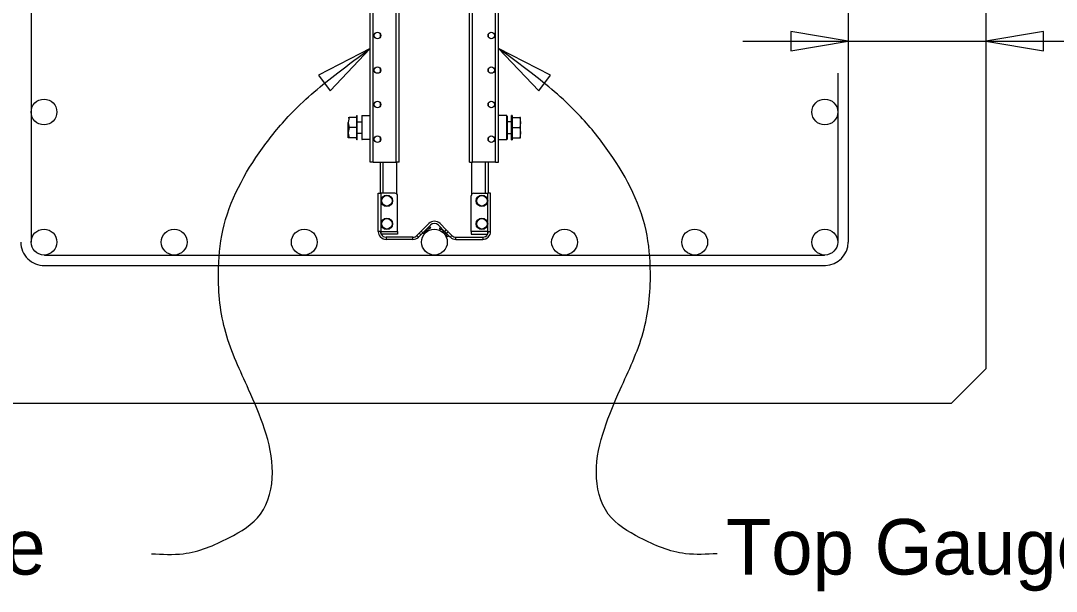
# Model space of a CAD drawing. Extents: x 0 to 36.1, y -3.7 to 15.
# Drawn here: x 2.543 to 4.42, y 5.937 to 6.972 of the extents above; entities that cross this region are included whole.
import ezdxf

# ---------------------------------------------------------------- set-up
doc = ezdxf.new("R2010")
doc.units = 0
for name, color, linetype in [('Leader', 7, 'Continuous'), ('Miscellaneous', 7, 'Continuous'), ('PileConc', 7, 'Continuous'), ('PlotBorder_dp', 7, 'Continuous'), ('PrestressSteel', 7, 'Continuous')]:
    doc.layers.add(name, color=color, linetype=linetype)

msp = doc.modelspace()

# ---------------------------------------------------------------- linework, layer by layer
at = {"layer": 'Leader'}
for points in [[(2.7804, 6.0056), (2.8378, 6.0056), (2.9204, 6.0343), (2.9778, 6.0774), (2.9994, 6.1527), (2.985, 6.2317), (2.9563, 6.3035), (2.9147, 6.4066), (2.9015, 6.5152), (2.9094, 6.592), (2.9814, 6.7414), (3.0353, 6.8061), (3.1178, 6.8779), (3.1768, 6.9218)], [(3.8057, 6.0056), (3.7483, 6.0056), (3.6657, 6.0343), (3.6083, 6.0774), (3.5867, 6.1527), (3.6011, 6.2317), (3.6298, 6.3035), (3.6714, 6.4066), (3.6846, 6.5152), (3.6767, 6.592), (3.6047, 6.7414), (3.5508, 6.8061), (3.4683, 6.8779), (3.4093, 6.9218)]]:
    msp.add_spline(points, degree=3, dxfattribs=at)
at = {"layer": 'Miscellaneous'}
for p, q in [((3.1768, 6.7159), (3.1768, 7.7123)), ((3.4093, 6.7159), (3.4093, 7.7123)), ((3.1821, 6.7159), (3.1821, 7.2312)), ((3.2239, 6.7159), (3.2239, 7.2284)), ((3.2292, 6.7159), (3.2292, 7.2284)), ((3.3569, 6.7159), (3.3569, 7.2284)), ((3.3622, 6.7159), (3.3622, 7.2284)), ((3.404, 6.7159), (3.404, 7.2312)), ((3.1951, 6.9429), (3.1951, 6.9481)), ((3.391, 6.9429), (3.391, 6.9481)), ((3.1951, 6.8802), (3.1951, 6.8855)), ((3.391, 6.8802), (3.391, 6.8855)), ((3.1951, 6.8176), (3.1951, 6.8229)), ((3.391, 6.8176), (3.391, 6.8229)), ((3.1383, 6.7968), (3.1366, 6.7876)), ((3.1366, 6.7968), (3.1383, 6.7968)), ((3.1519, 6.7968), (3.1383, 6.7968)), ((3.1515, 6.7968), (3.1521, 6.8004)), ((3.1519, 6.7968), (3.1519, 6.7785)), ((3.1521, 6.8004), (3.1533, 6.8004)), ((3.1521, 6.8004), (3.1521, 6.7566)), ((3.1533, 6.7566), (3.1533, 6.8004)), ((3.1613, 6.7995), (3.1613, 6.7575)), ((3.162, 6.8002), (3.1768, 6.8002)), ((3.162, 6.7568), (3.162, 6.8002)), ((3.4241, 6.8002), (3.4093, 6.8002)), ((3.4241, 6.7568), (3.4241, 6.8002)), ((3.4247, 6.7995), (3.4247, 6.7575)), ((3.434, 6.8004), (3.4327, 6.8004)), ((3.4327, 6.7566), (3.4327, 6.8004)), ((3.4346, 6.7968), (3.434, 6.8004)), ((3.434, 6.8004), (3.434, 6.7566)), ((3.4341, 6.7968), (3.4341, 6.7785)), ((3.4341, 6.7968), (3.4478, 6.7968)), ((3.4478, 6.7968), (3.4494, 6.7876)), ((3.4494, 6.7968), (3.4478, 6.7968)), ((3.4494, 6.7876), (3.4494, 6.7968)), ((3.1366, 6.7694), (3.1366, 6.7876)), ((3.1383, 6.7785), (3.1366, 6.7694)), ((3.1519, 6.7785), (3.1383, 6.7785)), ((3.1519, 6.7785), (3.1519, 6.7602)), ((3.1533, 6.7889), (3.1613, 6.7889)), ((3.4327, 6.7889), (3.4247, 6.7889)), ((3.4341, 6.7785), (3.4341, 6.7602)), ((3.4341, 6.7785), (3.4478, 6.7785)), ((3.4478, 6.7785), (3.4494, 6.7694)), ((3.4494, 6.7694), (3.4494, 6.7876)), ((3.1366, 6.7602), (3.1366, 6.7694)), ((3.1383, 6.7602), (3.1366, 6.7602)), ((3.1519, 6.7602), (3.1383, 6.7602)), ((3.1521, 6.7566), (3.1515, 6.7602)), ((3.1613, 6.7681), (3.1533, 6.7681)), ((3.1951, 6.755), (3.1951, 6.7603)), ((3.391, 6.755), (3.391, 6.7603)), ((3.4247, 6.7681), (3.4327, 6.7681)), ((3.434, 6.7566), (3.4346, 6.7602)), ((3.4341, 6.7602), (3.4478, 6.7602)), ((3.4478, 6.7602), (3.4494, 6.7602)), ((3.4494, 6.7602), (3.4494, 6.7694)), ((3.1533, 6.7566), (3.1521, 6.7566)), ((3.1768, 6.7568), (3.162, 6.7568)), ((3.4093, 6.7568), (3.4241, 6.7568)), ((3.4327, 6.7566), (3.434, 6.7566)), ((3.1821, 6.7159), (3.1768, 6.7159)), ((3.1821, 6.7159), (3.2239, 6.7159)), ((3.1951, 6.6596), (3.1951, 6.7159)), ((3.2004, 6.6596), (3.2004, 6.7159)), ((3.2292, 6.7159), (3.2239, 6.7159)), ((3.2252, 6.6579), (3.2252, 6.7159)), ((3.3569, 6.7159), (3.3622, 6.7159)), ((3.3609, 6.6579), (3.3609, 6.7159)), ((3.404, 6.7159), (3.3622, 6.7159)), ((3.3857, 6.6596), (3.3857, 6.7159)), ((3.391, 6.6596), (3.391, 6.7159)), ((3.404, 6.7159), (3.4093, 6.7159)), ((3.1911, 6.6596), (3.1963, 6.6596)), ((3.1911, 6.5902), (3.1911, 6.6596)), ((3.2214, 6.6596), (3.1963, 6.6596)), ((3.1963, 6.5902), (3.1963, 6.6596)), ((3.2264, 6.5902), (3.2264, 6.6546)), ((3.3597, 6.5902), (3.3597, 6.6546)), ((3.3647, 6.6596), (3.3897, 6.6596)), ((3.3897, 6.5902), (3.3897, 6.6596)), ((3.395, 6.6596), (3.3897, 6.6596)), ((3.395, 6.5902), (3.395, 6.6596)), ((3.1963, 6.5902), (3.1911, 6.5902)), ((3.1963, 6.585), (3.1963, 6.5902)), ((3.1963, 6.5902), (3.2264, 6.5902)), ((3.2264, 6.5902), (3.2264, 6.585)), ((3.2692, 6.5907), (3.2828, 6.6043)), ((3.2721, 6.5879), (3.2692, 6.5907)), ((3.2857, 6.6015), (3.2721, 6.5879)), ((3.2771, 6.5911), (3.2786, 6.5896)), ((3.2786, 6.5926), (3.2801, 6.5911)), ((3.2811, 6.5951), (3.2802, 6.596)), ((3.2807, 6.5947), (3.2821, 6.5932)), ((3.2827, 6.5967), (3.2842, 6.5953)), ((3.2852, 6.5992), (3.2843, 6.6001)), ((3.2848, 6.5988), (3.2863, 6.5974)), ((3.3116, 6.5902), (3.3004, 6.6015)), ((3.3034, 6.5967), (3.302, 6.5952)), ((3.3039, 6.5979), (3.3031, 6.5971)), ((3.3033, 6.6043), (3.3145, 6.5931)), ((3.3055, 6.5946), (3.3041, 6.5931)), ((3.3091, 6.591), (3.3076, 6.5896)), ((3.311, 6.5909), (3.3101, 6.59)), ((3.3145, 6.5931), (3.3116, 6.5902)), ((3.3597, 6.5902), (3.3597, 6.585)), ((3.3897, 6.5902), (3.3597, 6.5902)), ((3.3897, 6.585), (3.3897, 6.5902)), ((3.3897, 6.5902), (3.395, 6.5902)), ((3.2264, 6.585), (3.1963, 6.585)), ((3.2055, 6.5798), (3.2055, 6.5758)), ((3.254, 6.5798), (3.2055, 6.5798)), ((3.254, 6.5758), (3.2055, 6.5758)), ((3.254, 6.5758), (3.254, 6.5798)), ((3.2657, 6.5872), (3.2614, 6.5828)), ((3.2614, 6.5828), (3.2642, 6.58)), ((3.2685, 6.5843), (3.2642, 6.58)), ((3.2657, 6.5872), (3.2685, 6.5843)), ((3.2717, 6.5875), (3.2726, 6.5866)), ((3.2729, 6.587), (3.2744, 6.5855)), ((3.275, 6.5891), (3.2765, 6.5876)), ((3.3105, 6.5896), (3.3091, 6.5881)), ((3.3126, 6.5875), (3.3111, 6.586)), ((3.3162, 6.5839), (3.3147, 6.5825)), ((3.3152, 6.5867), (3.318, 6.5895)), ((3.3152, 6.5867), (3.3219, 6.58)), ((3.3183, 6.5819), (3.3168, 6.5804)), ((3.318, 6.5895), (3.3247, 6.5828)), ((3.3186, 6.5815), (3.3195, 6.5824)), ((3.3247, 6.5828), (3.3219, 6.58)), ((3.3321, 6.5758), (3.3321, 6.5798)), ((3.3321, 6.5798), (3.3806, 6.5798)), ((3.3321, 6.5758), (3.3806, 6.5758)), ((3.3597, 6.585), (3.3897, 6.585)), ((3.3806, 6.5798), (3.3806, 6.5758))]:
    msp.add_line(p, q, dxfattribs=at)
for points in [[(3.1366, 6.7876), (3.1367, 6.787), (3.1383, 6.7785)], [(3.4494, 6.7876), (3.4494, 6.787), (3.4478, 6.7785)], [(3.1366, 6.7694), (3.1367, 6.7687), (3.1383, 6.7602)], [(3.4494, 6.7694), (3.4494, 6.7687), (3.4478, 6.7602)], [(3.2692, 6.5907), (3.2686, 6.59), (3.2679, 6.5894), (3.2673, 6.5887), (3.2667, 6.5882), (3.2663, 6.5878), (3.266, 6.5874), (3.2658, 6.5872), (3.2657, 6.5872)], [(3.275, 6.5891), (3.2755, 6.5895), (3.2759, 6.5899), (3.2763, 6.5904), (3.2768, 6.5908), (3.2773, 6.5913), (3.2777, 6.5917), (3.2782, 6.5922), (3.2786, 6.5926)], [(3.2786, 6.5896), (3.2787, 6.5898), (3.2789, 6.59), (3.2792, 6.5902), (3.2794, 6.5905), (3.2797, 6.5908), (3.28, 6.5911), (3.2801, 6.5911)], [(3.2801, 6.5911), (3.2804, 6.5915), (3.2807, 6.5918), (3.281, 6.5921), (3.2813, 6.5924), (3.2815, 6.5926), (3.2818, 6.5928), (3.282, 6.593), (3.2821, 6.5932)], [(3.2807, 6.5947), (3.2808, 6.5949), (3.281, 6.595), (3.281, 6.5951), (3.2811, 6.5951)], [(3.2811, 6.5951), (3.2814, 6.5954), (3.2818, 6.5959), (3.2823, 6.5963), (3.2827, 6.5967)], [(3.2842, 6.5953), (3.2845, 6.5956), (3.2848, 6.5959), (3.2851, 6.5962), (3.2854, 6.5965), (3.2857, 6.5967), (3.2859, 6.597), (3.2861, 6.5972), (3.2863, 6.5974)], [(3.2848, 6.5988), (3.285, 6.599), (3.2851, 6.5991), (3.2852, 6.5992), (3.2852, 6.5992)], [(3.302, 6.5952), (3.3021, 6.595), (3.3023, 6.5948), (3.3026, 6.5946), (3.3028, 6.5943), (3.3031, 6.5941), (3.3034, 6.5938), (3.3037, 6.5934), (3.3041, 6.5931)], [(3.3031, 6.5971), (3.3031, 6.597), (3.3032, 6.597), (3.3033, 6.5968), (3.3034, 6.5967)], [(3.3055, 6.5946), (3.306, 6.5941), (3.3064, 6.5937), (3.3069, 6.5933), (3.3073, 6.5928), (3.3078, 6.5923), (3.3082, 6.5919), (3.3087, 6.5915), (3.3091, 6.591)], [(3.3101, 6.59), (3.3102, 6.5899), (3.3102, 6.5899), (3.3104, 6.5897), (3.3105, 6.5896)], [(3.3116, 6.5902), (3.3123, 6.5895), (3.313, 6.5889), (3.3136, 6.5883), (3.3141, 6.5877), (3.3146, 6.5873), (3.3149, 6.587), (3.3151, 6.5868), (3.3152, 6.5867)], [(3.318, 6.5895), (3.3179, 6.5896), (3.3177, 6.5898), (3.3174, 6.5901), (3.317, 6.5906), (3.3164, 6.5911), (3.3158, 6.5917), (3.3152, 6.5924), (3.3145, 6.5931)], [(3.2685, 6.5843), (3.2686, 6.5844), (3.2688, 6.5846), (3.2691, 6.5849), (3.2696, 6.5854), (3.2701, 6.5859), (3.2707, 6.5865), (3.2714, 6.5872), (3.2721, 6.5879)], [(3.2726, 6.5866), (3.2726, 6.5866), (3.2727, 6.5867), (3.2728, 6.5868), (3.2729, 6.587)], [(3.2744, 6.5855), (3.2746, 6.5857), (3.2748, 6.5859), (3.275, 6.5861), (3.2753, 6.5863), (3.2756, 6.5866), (3.2759, 6.5869), (3.2762, 6.5872), (3.2765, 6.5876)], [(3.3076, 6.5896), (3.3079, 6.5892), (3.3083, 6.5889), (3.3086, 6.5886), (3.3088, 6.5883), (3.3091, 6.5881)], [(3.3091, 6.5881), (3.3092, 6.5879), (3.3094, 6.5877), (3.3097, 6.5875), (3.3099, 6.5872), (3.3102, 6.587), (3.3105, 6.5867), (3.3108, 6.5863), (3.3111, 6.586)], [(3.3126, 6.5875), (3.313, 6.5871), (3.3135, 6.5866), (3.3139, 6.5862), (3.3144, 6.5857), (3.3148, 6.5853), (3.3153, 6.5848), (3.3157, 6.5844), (3.3162, 6.5839)], [(3.3147, 6.5825), (3.315, 6.5821), (3.3153, 6.5818), (3.3156, 6.5815), (3.3159, 6.5812), (3.3162, 6.581), (3.3164, 6.5807), (3.3166, 6.5805), (3.3168, 6.5804)], [(3.3183, 6.5819), (3.3184, 6.5817), (3.3185, 6.5816), (3.3186, 6.5815), (3.3186, 6.5815)]]:
    msp.add_lwpolyline(points, dxfattribs=at)
for centre, radius in [((3.1898, 6.9455), 0.00589), ((3.3962, 6.9455), 0.00589), ((3.1898, 6.8829), 0.00589), ((3.3962, 6.8829), 0.00589), ((3.1898, 6.8203), 0.00589), ((3.3962, 6.8203), 0.00589), ((3.1898, 6.7576), 0.00589), ((3.3962, 6.7576), 0.00589), ((3.2069, 6.6458), 0.0104), ((3.2069, 6.6458), 0.00951), ((3.3792, 6.6458), 0.0104), ((3.3792, 6.6458), 0.00951), ((3.2069, 6.604), 0.0104), ((3.2069, 6.604), 0.00951), ((3.3792, 6.604), 0.0104), ((3.3792, 6.604), 0.00951)]:
    msp.add_circle(centre, radius, dxfattribs=at)
for centre, radius, start, end in [((3.162, 6.7995), 0.000668, 90, 180), ((3.4241, 6.7995), 0.000668, 0, 90), ((3.162, 6.7575), 0.000668, 180, 270), ((3.4241, 6.7575), 0.000668, 270, 0), ((3.2214, 6.6546), 0.00501, 0, 90), ((3.3647, 6.6546), 0.00501, 90, 180), ((3.293, 6.5941), 0.0144, 45, 135), ((3.2055, 6.5902), 0.0144, 180, 270), ((3.2055, 6.5902), 0.0104, 180, 208.3576), ((3.293, 6.5941), 0.0104, 45, 135), ((3.3806, 6.5902), 0.0144, 270, 0), ((3.3806, 6.5902), 0.0104, 331.6424, 0), ((3.2055, 6.5902), 0.0104, 210.265, 270), ((3.254, 6.5902), 0.0104, 270, 315), ((3.254, 6.5902), 0.0144, 270, 315), ((3.3321, 6.5902), 0.0144, 225, 270), ((3.3321, 6.5902), 0.0104, 225, 270), ((3.3806, 6.5902), 0.0104, 270, 329.735)]:
    msp.add_arc(centre, radius, start, end, dxfattribs=at)
at = {"layer": 'PileConc'}
for p, q in [((4.293, 8.2161), (4.293, 6.3411)), ((4.293, 6.3411), (4.2305, 6.2786)), ((2.3555, 6.2786), (4.2305, 6.2786))]:
    msp.add_line(p, q, dxfattribs=at)
at = {"layer": 'PlotBorder_dp'}
for p, q in [((3.8524, 6.9353), (4.043, 6.9353)), ((4.043, 6.9353), (4.293, 6.9353)), ((4.293, 6.9353), (5.1697, 6.9353))]:
    msp.add_line(p, q, dxfattribs=at)
for points in [[(4.043, 6.9353), (3.9389, 6.9529), (3.9389, 6.9176)], [(4.293, 6.9353), (4.3972, 6.9176), (4.3972, 6.9529)], [(3.1768, 6.9218), (3.0828, 6.8737), (3.1039, 6.8454)], [(3.4093, 6.9218), (3.4822, 6.8454), (3.5033, 6.8737)]]:
    msp.add_lwpolyline(points, close=True, dxfattribs=at)
at = {"layer": 'PrestressSteel'}
for p, q in [((2.5618, 7.9864), (2.5618, 6.5708)), ((4.043, 7.9864), (4.043, 6.5708)), ((4.0242, 6.8772), (4.0242, 6.5708)), ((2.5861, 6.5474), (4, 6.5474)), ((2.5862, 6.5286), (4.0017, 6.5286))]:
    msp.add_line(p, q, dxfattribs=at)
for centre in [(2.5853, 6.8068), (4.0008, 6.8068), (2.5853, 6.5708), (2.8212, 6.5708), (3.0571, 6.5708), (3.293, 6.5708), (3.529, 6.5708), (3.7649, 6.5708), (4.0008, 6.5708)]:
    msp.add_circle(centre, 0.0234, dxfattribs=at)
for centre, start, end in [((2.5853, 6.5708), 180, 271.2723), ((4.0008, 6.5708), 271.2723, 0)]:
    msp.add_arc(centre, 0.0423, start, end, dxfattribs=at)

# ---------------------------------------------------------------- texts
at = {"layer": 'PlotBorder_dp'}
for s, p in [('Tip Gauge', (1.9587, 5.9677)), ('Top Gauge', (3.8214, 5.9677))]:
    msp.add_text(s, height=0.1008, dxfattribs=at).set_placement(p)

doc.saveas('drawing.dxf')
